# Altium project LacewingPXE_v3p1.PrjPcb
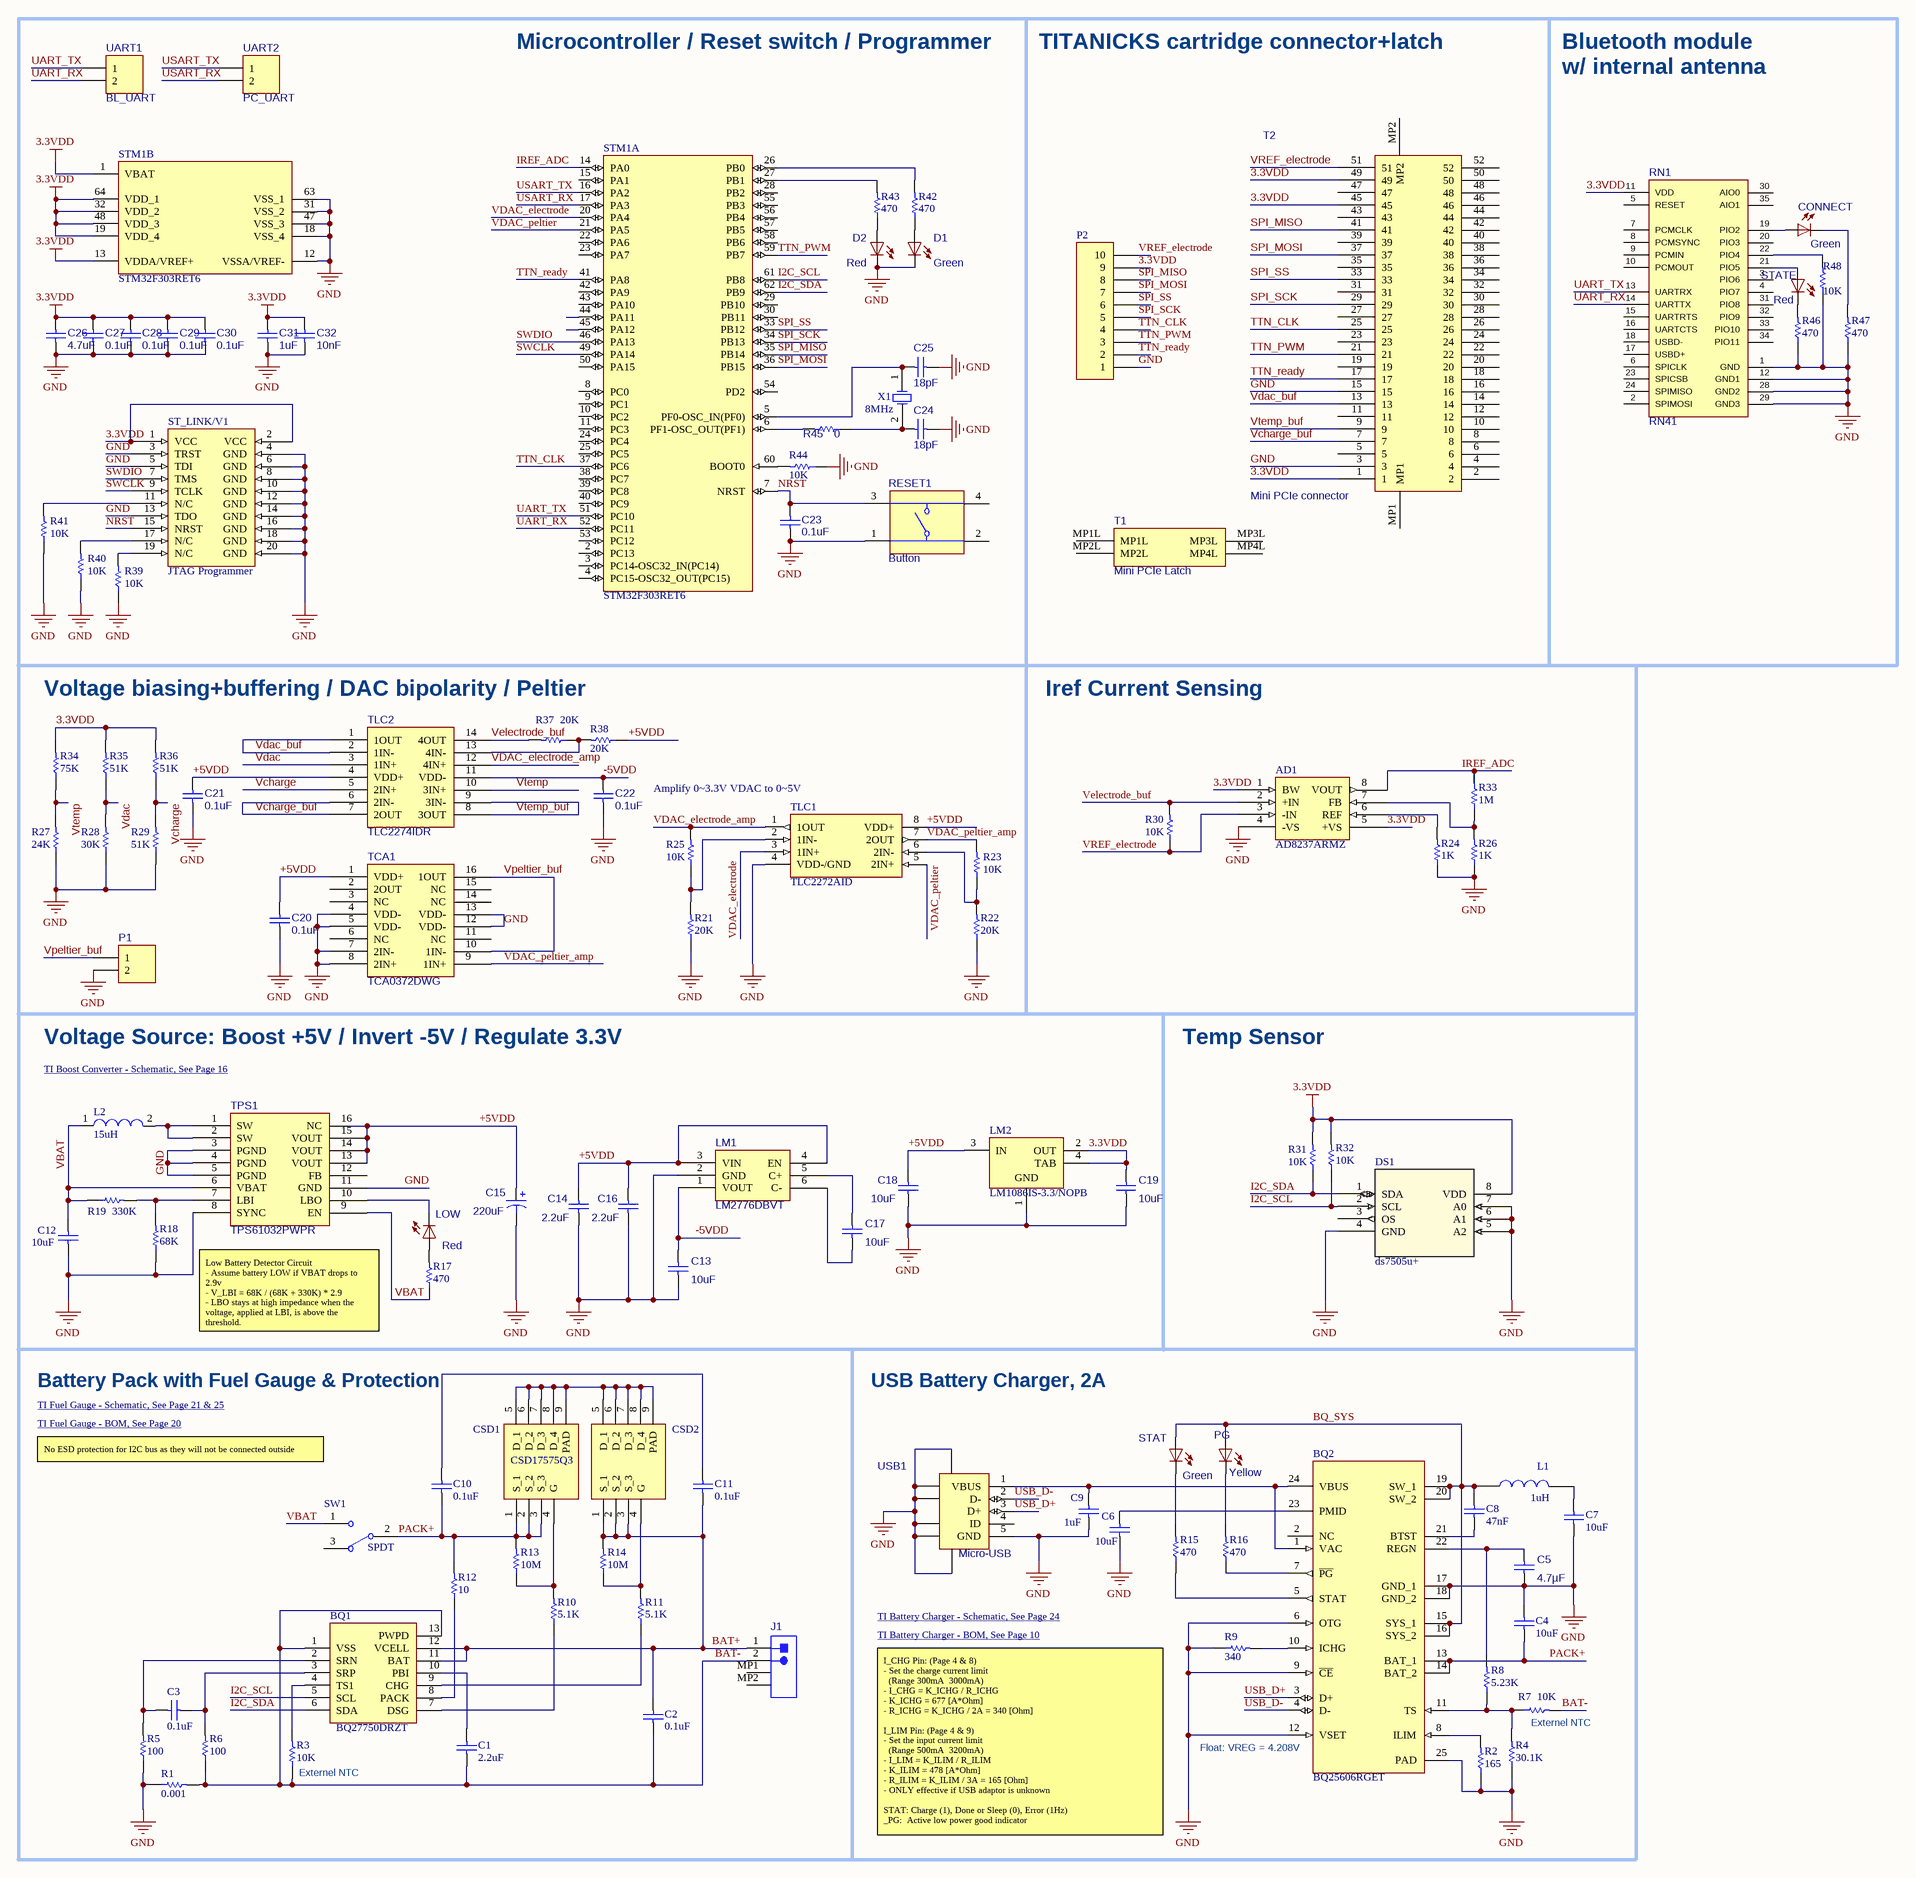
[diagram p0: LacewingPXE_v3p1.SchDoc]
1 sheet, 114 parts. Net scope: global (net labels, ports and power ports of the same name join across sheets).
Board file: LacewingPXE_v3p1.PcbDoc

## Sheet LacewingPXE_v3p1.SchDoc
size A2

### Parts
AD1  AD8237ARMZ  [ADI-RM-8_N]
BQ1  BQ27750DRZT  [BQ27510DRZTG3]
BQ2  BQ25606RGET  [QFN50P400X400X100-25N]
C1  2.2uF  [CAPC1005X55X25NL05T10]
C2  0.1uF  [CAPC1005X56X25LL10T15]
C3  0.1uF  [CAPC1005X56X25LL10T15]
C4  10uF  [CAPC2013X140X50ML20T25]
C5  4.7µF  [CAPC0603(1608)100_N]
C6  10uF  [CAPC2013X95X45NL10T25]
C7  10uF  [CAPC2013X140X50ML20T25]
C8  47nF  [CAPC1005X55X25NL05T10]
C9  1uF  [CAPC2013X95X45NL10T25]
C10  0.1uF  [CAPC1005X56X25LL10T15]
C11  0.1uF  [CAPC1005X56X25LL10T15]
C12  10uF  [CAPC2013X140X50NL20T25]
C13  10uF  [CAPC0805(2012)75_N]
C14  2.2uF  [CAPC0805(2012)75_N]
C15  220uF  [AVX-CAPC7343_V]
C16  2.2uF  [CAPC0805(2012)75_N]
C17  10uF  [CAPC0805(2012)75_N]
C18  10uF  [CAPC0805(2012)75_N]
C19  10uF  [CAPC0805(2012)75_N]
C20  0.1uF  [CAPC0603(1608)100_N]
C21  0.1uF  [CAPC0603(1608)100_N]
C22  0.1uF  [CAPC0603(1608)100_N]
C23  0.1uF  [CAPC0603(1608)100_N]
C24  18pF  [CAPC0603(1608)100_N]
C25  18pF  [CAPC0603(1608)100_N]
C26  4.7uF  [CAPC0603(1608)100_N]
C27  0.1uF  [CAPC0603(1608)100_N]
C28  0.1uF  [CAPC0603(1608)100_N]
C29  0.1uF  [CAPC0603(1608)100_N]
C30  0.1uF  [CAPC0603(1608)100_N]
C31  1uF  [CAPC0603(1608)100_N]
C32  10nF  [CAPC0603(1608)100_N]
CONNECT  Green  [LED-0603]
CSD1  CSD17575Q3  [CSD16327]
CSD2  CSD17575Q3  [CSD16327]  (value not drawn)
D1  Green  [LED-0603]
D2  Red  [LED-0603]
DS1  ds7505u+  [21-0036K]
J1  (no value)  [JST- S2B-PH-SM4-TB(LF)(SN)-2_V]
L1  1uH  [INDC2520X120N]
L2  15uH  [WE-PD 1050]
LM1  LM2776DBVT  [TI-DBV6_M]
LM2  LM1086IS-3.3/NOPB  [KTT0003B_N]
LOW  Red  [LED-0603]
P1  (no value)  [HDR1X2]
P2  (no value)  [HDR1X10]
PG  Yellow  [LED-0603]
R1  0.001  [RESC3216X89X104LL25T25]
R2  165  [RESC1005X40X25NL05T05]
R3  10K  [RESC1005X40X25LL05T05]
R4  30.1K  [RESC1005X40X25LL05T05]
R5  100  [RESC1005X40X25NL05T05]
R6  100  [RESC1005X40X25NL05T05]
R7  10K  [RESC1005X40X25LL05T05]
R8  5.23K  [RESC1005X40X25LL05T05]
R9  340  [RESC1005X40X25LL05T05]
R10  5.1K  [RESC0402(1005)_N]
R11  5.1K  [RESC0402(1005)_N]
R12  10  [RESC1005X40X25NL05T05]
R13  10M  [RESC1005X40X25LL05T05]
R14  10M  [RESC1005X40X25LL05T05]
R15  470  [RESC1005X40X25LL05T05]
R16  470  [RESC1005X40X25LL05T05]
R17  470  [RESC1005X40X25LL05T05]
R18  68K  [RESC1005X40X25ML05T05]
R19  330K  [RESC1005X40X25NL05T05]
R21  20K  [RESC1005X40X25NL05T05]
R22  20K  [RESC1005X40X25NL05T05]
R23  10K  [RESC1005X40X25NL05T05]
R24  1K  [RESC1005X40X25NL05T05]
R25  10K  [RESC1005X40X25NL05T05]
R26  1K  [RESC1005X40X25NL05T05]
R27  24K  [RESC1005X40X25ML05T05]
R28  30K  [RESC1005X40X25LL05T05]
R29  51K  [RESC1005X40X25ML05T05]
R30  10K  [RESC1005X40X25NL05T05]
R31  10K  [RESC1005X40X25NL05T05]
R32  10K  [RESC1005X40X25NL05T05]
R33  1M  [RESC1005X40X25NL05T05]
R34  75K  [RESC1005X40X25LL05T05]
R35  51K  [RESC1005X40X25ML05T05]
R36  51K  [RESC1005X40X25ML05T05]
R37  20K  [RESC1005X40X25NL05T05]
R38  20K  [RESC1005X40X25NL05T05]
R39  10K  [RESC1005X40X25NL05T05]
R40  10K  [RESC1005X40X25NL05T05]
R41  10K  [RESC1005X40X25NL05T05]
R42  470  [RESC1005X40X25LL05T05]
R43  470  [RESC1005X40X25LL05T05]
R44  10K  [RESC1005X40X25NL05T05]
R45  0  [RESC0603(1608)_N]
R46  470  [RESC1005X40X25LL05T05]
R47  470  [RESC1005X40X25LL05T05]
R48  10K  [RESC1005X40X25NL05T05]
RESET1  Button  [OMRON-B3F-1000-4_V]
RN1  RN41  [RN41]
ST_LINK/V1  JTAG Programmer  [JTAG2]
STAT  Green  [LED-0603]
STATE  Red  [LED-0603]
STM1  STM32F303RET6  [STM-LQFP64_V]  (parts A,B of 2)
SW1  SPDT  [1000-SERIES(SPDT)]
T1  Mini PCIe Latch  [Molex Latch-48099]
T2  Mini PCIe connector  [Molex Conn-67910]
TCA1  TCA0372DWG  [ONSC-SOIC-16-751G-03_V]
TLC1  TLC2272AID  [SOIC127P600X175-8N]
TLC2  TLC2274IDR  [TI-D14_M]
TPS1  TPS61032PWPR  [PW0016A_M]
UART1  BL_UART  [HDR1X2]
UART2  PC_UART  [HDR1X2]
USB1  Micro-USB  [HIRO-ZX62R-B-5P_V]
X1  8MHz  [QCL]

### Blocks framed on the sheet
Microcontroller / Reset switch / Programmer: C23-C32 D1 D2 R39-R45 RESET1 ST_LINK/V1 STM1 UART1 UART2 X1
TITANICKS cartridge connector+latch: P2 T1 T2
Voltage biasing+buffering / DAC bipolarity / Peltier: C20-C22 P1 R21-R23 R25 R27-R29 R34-R38 TCA1 TLC1 TLC2
Iref Current Sensing: AD1 R24 R26 R30 R33
Voltage Source: Boost +5V / Invert -5V / Regulate 3.3V: C12-C19 L2 LM1 LM2 LOW R17-R19 TPS1
Temp Sensor: DS1 R31 R32
Battery Pack with Fuel Gauge & Protection: BQ1 C1-C3 C10 C11 CSD1 CSD2 J1 R1 R3 R5 R6 R10-R14 SW1
USB Battery Charger, 2A: BQ2 C4-C9 L1 PG R2 R4 R7-R9 R15 R16 STAT USB1

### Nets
3.3VDD: AD1.1(BW) AD1.5(+VS) C19.1 C26.1 C27.1 C28.1 C29.1 C30.1 C31.1 C32.1 DS1.8(VDD) LM2.2(OUT) LM2.4(TAB) P2.9 R31.2 R32.2 R34.2 R35.2 R36.2 RN1.11(VDD) ST_LINK/V1.1(VCC) ST_LINK/V1.2(VCC) STM1.1(VBAT) STM1.13(VDDA/VREF+) STM1.19(VDD_4) STM1.32(VDD_2) STM1.48(VDD_3) STM1.64(VDD_1) T2.1 T2.45 T2.49
GND: AD1.4(-VS) BQ2.6(OTG) BQ2.9(~{CE}) BQ2.12(VSET) BQ2.17(GND_1) BQ2.18(GND_2) BQ2.25(PAD) C4.2 C5.1 C6.1 C7.1 C9.1 C12.1 C13.2 C14.1 C15.2 C16.1 C18.2 C19.2 C20.2 C21.2 C22.2 C23.2 C24.2 C25.2 C26.2 C27.2 C28.2 C29.2 C30.2 C31.2 C32.2 D1.C D2.C DS1.4(GND) DS1.5(A2) DS1.6(A1) DS1.7(A0) LM1.2(GND) LM2.1(GND) P1.2 P2.1 R1.1 R2.1 R4.1 R5.1 R9.1 R18.1 R21.1 R22.1 R24.1 R26.1 R27.1 R28.1 R29.1 R39.1 R40.1 R41.1 R44.1 R46.1 R47.1 R48.1 RESET1.1 RN1.1(GND) RN1.12(GND1) RN1.28(GND2) RN1.29(GND3) ST_LINK/V1.3(TRST) ST_LINK/V1.4(GND) ST_LINK/V1.5(TDI) ST_LINK/V1.6(GND) ST_LINK/V1.8(GND) ST_LINK/V1.10(GND) ST_LINK/V1.12(GND) ST_LINK/V1.13(TDO) ST_LINK/V1.14(GND) ST_LINK/V1.16(GND) ST_LINK/V1.18(GND) ST_LINK/V1.20(GND) STM1.12(VSSA/VREF-) STM1.18(VSS_4) STM1.31(VSS_2) STM1.47(VSS_3) STM1.63(VSS_1) T2.3 T2.15 TCA1.4(VDD-) TCA1.5(VDD-) TCA1.7(2IN-) TCA1.8(2IN+) TCA1.12(VDD-) TCA1.13(VDD-) TLC1.4(VDD-/GND) TPS1.3(PGND) TPS1.4(PGND) TPS1.5(PGND) TPS1.8(SYNC) TPS1.11(GND) USB1.5(GND) USB1.6(SHLD) USB1.7(SHLD) USB1.8(SHLD) USB1.9(SHLD) USB1.10(SHLD) USB1.11(SHLD)
+5VDD: C14.2 C15.1 C16.2 C18.1 C20.1 C21.1 LM1.3(VIN) LM1.4(EN) LM2.3(IN) R38.1 TCA1.1(VDD+) TLC1.8(VDD+) TLC2.4(VDD+) TPS1.13(VOUT) TPS1.14(VOUT) TPS1.15(VOUT) TPS1.16(NC)
-5VDD: C13.1 C22.1 LM1.1(VOUT) TLC2.11(VDD-)
BAT+: BQ1.11(BAT) BQ1.12(VCELL) C2.2 C11.1 CSD2.1(S_1) CSD2.2(S_2) CSD2.3(S_3) J1.1 R14.2
BAT-: BQ1.1(VSS) BQ1.13(PWPD) C1.1 C2.1 J1.2 R1.2 R3.1 R6.1 R7.2
BQ_SYS: BQ2.15(SYS_1) BQ2.16(SYS_2) BQ2.19(SW_1) BQ2.20(SW_2) C8.2 L1.1 PG.A STAT.A
I2C_SCL: BQ1.5(SCL) DS1.2(SCL) R32.1 STM1.61(PB8)
I2C_SDA: BQ1.6(SDA) DS1.1(SDA) R31.1 STM1.62(PB9)
IREF_ADC: AD1.8(VOUT) R33.2 STM1.14(PA0)
NRST: C23.1 RESET1.3 ST_LINK/V1.15(NRST) STM1.7(NRST)
PACK+: BQ2.13(BAT_1) BQ2.14(BAT_2) C4.1 C10.1 CSD1.1(S_1) CSD1.2(S_2) CSD1.3(S_3) R12.2 R13.2 SW1.2
SPI_MISO: P2.8 STM1.35(PB14) T2.41
SPI_MOSI: P2.7 STM1.36(PB15) T2.37
SPI_SCK: P2.5 STM1.34(PB13) T2.29
SPI_SS: P2.6 STM1.33(PB12) T2.33
SWCLK: ST_LINK/V1.9(TCLK) STM1.49(PA14)
SWDIO: ST_LINK/V1.7(TMS) STM1.46(PA13)
TTN_CLK: P2.4 STM1.37(PC6) T2.25
TTN_PWM: P2.3 STM1.59(PB7) T2.21
TTN_ready: P2.2 STM1.41(PA8) T2.17
UART_RX: RN1.14(UARTTX) STM1.52(PC11) UART1.2
UART_TX: RN1.13(UARTRX) STM1.51(PC10) UART1.1
USART_RX: STM1.17(PA3) UART2.2
USART_TX: STM1.16(PA2) UART2.1
USB_D+: BQ2.3(D+) USB1.3(D+)
USB_D-: BQ2.4(D-) USB1.2(D-)
VBAT: C12.2 L2.1 R17.1 R19.1 SW1.1 TPS1.6(VBAT) TPS1.9(EN)
Vcharge: R29.2 R36.1 TLC2.5(2IN+)
Vcharge_buf: T2.7 TLC2.6(2IN-) TLC2.7(2OUT)
Vdac: R28.2 R35.1 TLC2.3(1IN+)
Vdac_buf: T2.13 TLC2.1(1OUT) TLC2.2(1IN-)
VDAC_electrode: STM1.20(PA4) TLC1.3(1IN+)
VDAC_electrode_amp: R25.2 TLC1.1(1OUT) TLC2.12(4IN+)
VDAC_peltier: STM1.21(PA5) TLC1.5(2IN+)
VDAC_peltier_amp: R23.2 TCA1.9(1IN+) TLC1.7(2OUT)
Velectrode_buf: AD1.2(+IN) R30.2 R37.2 TLC2.14(4OUT)
Vpeltier_buf: P1.1 TCA1.10(1IN-) TCA1.16(1OUT)
VREF_electrode: AD1.3(-IN) P2.10 R30.1 T2.51
Vtemp: R27.2 R34.1 TLC2.10(3IN+)
Vtemp_buf: T2.9 TLC2.8(3OUT) TLC2.9(3IN-)
NetAD1_6: AD1.6(REF) R24.2
NetAD1_7: AD1.7(FB) R26.2 R33.1
NetBQ1_2: BQ1.2(SRN) C3.1 R5.2
NetBQ1_3: BQ1.3(SRP) C3.2 R6.2
NetBQ1_4: BQ1.4(TS1) R3.2
NetBQ1_7: BQ1.7(DSG) R10.1
NetBQ1_8: BQ1.8(PACK) R12.1
NetBQ1_9: BQ1.9(CHG) R11.1
NetBQ1_10: BQ1.10(PBI) C1.2
NetBQ2_1: BQ2.1(VAC) BQ2.24(VBUS) C9.2 USB1.1(VBUS)
NetBQ2_5: BQ2.5(STAT) R15.1
NetBQ2_7: BQ2.7(~{PG}) R16.1
NetBQ2_8: BQ2.8(ILIM) R2.2
NetBQ2_10: BQ2.10(ICHG) R9.2
NetBQ2_11: BQ2.11(TS) R4.2 R7.1 R8.1
NetBQ2_21: BQ2.21(BTST) C8.1
NetBQ2_22: BQ2.22(REGN) C5.2 R8.2
NetBQ2_23: BQ2.23(PMID) C6.2
NetC7_2: C7.2 L1.2
NetC10_2: C10.2 C11.2
NetC17_1: C17.1 LM1.5(C+)
NetC17_2: C17.2 LM1.6(C-)
NetC24_1: C24.1 R45.1 X1.2(OSC2)
NetC25_1: C25.1 STM1.5(PF0-OSC_IN(PF0)) X1.1(OSC1)
NetCONNECT_A: CONNECT.A RN1.19(PIO2)
NetCONNECT_C: CONNECT.C R47.2
NetCSD1_4: CSD1.4(G) R10.2 R13.1
NetCSD1_5: CSD1.5(D_1) CSD1.6(D_2) CSD1.7(D_3) CSD1.8(D_4) CSD1.9(PAD) CSD2.5(D_1) CSD2.6(D_2) CSD2.7(D_3) CSD2.8(D_4) CSD2.9(PAD)
NetCSD2_4: CSD2.4(G) R11.2 R14.1
NetD1_A: D1.A R42.1
NetD2_A: D2.A R43.1
NetL2_2: L2.2 TPS1.1(SW) TPS1.2(SW)
NetLOW_A: LOW.A R17.2
NetLOW_C: LOW.C TPS1.10(LBO)
NetPG_C: PG.C R16.2
NetR15_2: R15.2 STAT.C
NetR18_2: R18.2 R19.2 TPS1.7(LBI)
NetR21_2: R21.2 R25.1 TLC1.2(1IN-)
NetR22_2: R22.2 R23.1 TLC1.6(2IN-)
NetR37_1: R37.1 R38.2 TLC2.13(4IN-)
NetR39_2: R39.2 ST_LINK/V1.19(N/C)
NetR40_2: R40.2 ST_LINK/V1.17(N/C)
NetR41_2: R41.2 ST_LINK/V1.11(N/C)
NetR42_2: R42.2 STM1.26(PB0)
NetR43_2: R43.2 STM1.27(PB1)
NetR44_2: R44.2 STM1.60(BOOT0)
NetR45_2: R45.2 STM1.6(PF1-OSC_OUT(PF1))
NetR46_2: R46.2 STATE.C
NetR48_2: R48.2 RN1.22(PIO4)
NetRN1_21: RN1.21(PIO5) STATE.A

Not connected (* = marked no-connect by the designer): BQ2 2(NC); DS1 3(OS); J1 MP1 MP2; RESET1 2 4; RN1 2(SPIMOSI) 3(PIO6) 4(PIO7) 5(RESET) 6(SPICLK) 7(PCMCLK) 8(PCMSYNC) 9(PCMIN) 10(PCMOUT) 15(UARTRTS) 16(UARTCTS) 17(USBD+) 18(USBD-) 20(PIO3) 23(SPICSB) 24(SPIMISO) 30(AIO0) 31(PIO8) 32(PIO9) 33(PIO10) 34(PIO11) 35(AIO1); STM1 2(PC13) 3(PC14-OSC32_IN(PC14)) 4(PC15-OSC32_OUT(PC15)) 8(PC0) 9(PC1) 10(PC2) 11(PC3) 15(PA1) 22(PA6) 23(PA7) 24(PC4) 25(PC5) 28(PB2) 29(PB10) 30(PB11) 38(PC7) 39(PC8) 40(PC9) 42(PA9) 43(PA10) 44(PA11) 45(PA12) 50(PA15) 53(PC12) 54(PD2) 55(PB3) 56(PB4) 57(PB5) 58(PB6); SW1 3; T1 MP1L MP2L MP3L MP4L; T2 2 4 5 6 8 10 11 12 14 16 18 19 20 22 23 24 26 27 28 30 31 32 34 35 36 38 39 40 42 43 44 46 47 48 50 52 MP1 MP2; TCA1 2(2OUT) 3(NC) 6(NC) 11(NC) 14(NC) 15(NC); TPS1 12(FB); USB1 4(ID)

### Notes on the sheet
- Bluetooth module
- w/ internal antenna
- Amplify 0~3.3V VDAC to 0~5V
- TI Boost Converter - Schematic, See Page 16 <http://www.ti.com/lit/ds/symlink/tps61032.pdf>
- Low Battery Detector Circuit
  - Assume battery LOW if VBAT drops to 2.9v
  - V_LBI = 68K / (68K + 330K) * 2.9
  - LBO stays at high impedance when the voltage, applied at LBI, is above the threshold.
  It is active low when the voltage at LBI goes below 500 mV
- TI Fuel Gauge - Schematic, See Page 21 & 25 <http://www.ti.com/lit/ds/symlink/bq27750.pdf>
- TI Fuel Gauge - BOM, See Page 20 <http://www.ti.com/lit/ug/sluubp4/sluubp4.pdf>
- No ESD protection for I2C bus as they will not be connected outside
- TI Battery Charger - Schematic, See Page 24 <http://www.ti.com/lit/ds/symlink/bq25606.pdf>
- TI Battery Charger - BOM, See Page 10 <http://www.ti.com/lit/ug/sluubl3a/sluubl3a.pdf>
- (near R7) Externel NTC
- (near R3) Externel NTC
- (near BQ2) Float: VREG = 4.208V
- I_CHG Pin: (Page 4 & 8)
  - Set the charge current limit
  (Range 300mA  3000mA)
  - I_CHG = K_ICHG / R_ICHG
  - K_ICHG = 677 [A*Ohm]
  - R_ICHG = K_ICHG / 2A = 340 [Ohm]
  I_LIM Pin: (Page 4 & 9)
  - Set the input current limit
  (Range 500mA  3200mA)
  - I_LIM = K_ILIM / R_ILIM
  - K_ILIM = 478 [A*Ohm]
  - R_ILIM = K_ILIM / 3A = 165 [Ohm]
  - ONLY effective if USB adaptor is unknown
  STAT: Charge (1), Done or Sleep (0), Error (1Hz)
  _PG:  Active low power good indicator

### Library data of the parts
AD1 = AD8237: Instrument Amplifier; Manufacturer: ANALOG DEVICES
BQ1 = BQ27750DRZT: Fuel Gauge and Protection; Manufacturer: TEXAS INSTRUMENTS
BQ2 = BQ25606RGET: Battery Charger; Manufacturer: TEXAS INSTRUMENTS
C1 = CMP-2008-04630-4: CAP 0402; Manufacturer: Murata; Part No: GRM155R60J225KE95D
C2 C3 C10 C11 = CMP-2008-02743-1: CAP 0402; Manufacturer: AVX; Part No: 04026D104KAT2A
C4 C7 = CMP-2007-04702-1: CAP 0805; Manufacturer: AVX; Part No: 0805ZC106KAT2A
C5 = CAP: CAP 0603; Manufacturer: Murata; Part No: GRM188R61C475KAAJD
C6 = CMP-2007-00191-1: CAP 0805; Manufacturer: Murata; Part No: GRM21BC71E106KE11L
C8 = CMP-2008-04630-4: CAP 0402; Manufacturer: Murata; Part No: GRM155R71E473KA88D
C9 = CMP-2007-00191-1: CAP 0805; Manufacturer: Murata; Part No: GRM219R71E105KA88D
C12 = CMP-2007-04643-1: CAP 0805; Manufacturer: AVX; Part No: 08056D106KAT2A
C13 C17-C19 = CMP-1036-00002-1: CAP 0805; Manufacturer: Wurth Electronics; Part No: 885012107010
C14 C16 = CMP-1036-00002-1: CAP 0805; Manufacturer: Multicomp; Part No: MC0805B225K250CT
C15 = CMP-0279-00002-1: CAP 2917; Manufacturer: AVX; Part No: TAJD227K010RNJ
C20-C23 C27-C30 = CMP-1035-00032-1: CAP 0603; Manufacturer: Multicomp; Part No: MC0603B104K500CT
C24 C25 = CMP-1035-00032-1: CAP 0603; Manufacturer: KEMET; Part No: C0603C180K5RACTU
C26 = CMP-1035-00032-1: CAP 0603; Manufacturer: AVX; Part No: 06036D475KAT2A
C31 = CMP-1035-00032-1: CAP 0603; Manufacturer: AVX; Part No: 06033D105KAT2A
C32 = CMP-1035-00032-1: CAP 0603; Manufacturer: KEMET; Part No: C0603C103K5RAC7081
CONNECT D1 = LED0603: LED SMD 0603; Manufacturer: KingBright; Part No: KPT-1608SGC
CSD1 CSD2 = CSD17575Q3: MOSFET; Manufacturer: Texas Instruments; Part No: CSD17575Q3T
D2 LOW STATE = LED0603: LED SMD 0603; Manufacturer: KingBright; Part No: KPT-1608SECK-J3
DS1 = ds7505u+: Digital Thermometer; Manufacturer: Maxim
J1 = CN-1P-2M-R2: Battery Connector; Manufacturer: JST; Part No: S2B-PH-SM4-TB(LF)(SN)
L1 = DFE252012F-1R0M=P2: Inductor; Manufacturer: Murata
L2 = CMP-1396-00032-1: Power Inductor; Manufacturer: Wurth Elektronik; Part No: 7447714150
LM1 = LM2776: Voltage Inverter -5V; Manufacturer: Texas Instruments
LM2 = CMP-0062-00552-5: 1.5A 3.3V LDO; Manufacturer: Texas Instruments
P1 UART1 UART2 = Header 2: Header, 2-Pin
P2 = Header 10: Header, 10-Pin
PG = LED0603: LED SMD 0603; Manufacturer: Kingbright; Part No: KPT-1608SYCK-J3
R1 = CMP-1666-00018-2: RES 1206; Manufacturer: Vishay; Part No: WSLP12061L000FEA
R2 = CMP-2002-08233-1: RES 0402; Manufacturer: Vishay Dale; Part No: CRCW0402165RFKED
R3 R7 = CMP-2002-01179-1: Thermistor RES 0402; Manufacturer: Panasonic; Part No: ERTJ0EG103FA
R4 = CMP-2002-08506-3: RES 0402; Manufacturer: Vishay; Part No: CRCW040230K1FKED
R5 R6 = CMP-2002-08127-1: RES 0402; Manufacturer: Vishay; Part No: CRCW0402100RFKED
R8 = CMP-2002-00118-3: RES 0402; Manufacturer: Vishay; Part No: CRCW04025K23FKED
R9 = CMP-2002-00876-1: RES 0402; Manufacturer: Panasonic; Part No: ERJ2RKF3400X
R10 R11 = CMP-1011-00590-1: RES 0402; Manufacturer: Vishay; Part No: CRCW04025K10FKED
R12 = CMP-2002-08143-1: RES 0402; Manufacturer: Vishay Dale; Part No: CRCW040210R0FKED
R13 R14 = CMP-2002-08141-1: RES 0402; Manufacturer: Vishay; Part No: CRCW040210M0FKED
R15-R17 R42 R43 R46 R47 = CMP-2002-00022-1: RES 0402; Manufacturer: Vishay; Part No: CRCW0402470RFKED
R18 = CMP-2002-00170-1: RES 0402; Manufacturer: Vishay; Part No: CRCW040268K0FKED
R19 = CMP-2002-08521-1: RES 0402; Manufacturer: Vishay; Part No: CRCW0402330KFKED
R21 R22 R37 R38 = CMP-2002-08356-1: RES 0402; Manufacturer: Vishay; Part No: CRCW040220K0FKED
R23 R25 R30-R32 R39-R41 R44 R48 = CMP-2002-08135-1: RES 0402; Manufacturer: Vishay; Part No: CRCW040210K0FKED
R24 R26 = CMP-2002-08276-1: RES 0402; Manufacturer: Vishay; Part No: CRCW04021K00FKED
R27 = CMP-2002-08403-1: RES 0402; Manufacturer: Vishay Dale; Part No: CRCW040224K0FKED
R28 = CMP-2002-08504-1: RES 0402; Manufacturer: Vishay Dale; Part No: CRCW040230K0FKED
R29 R35 R36 = CMP-2002-00078-1: RES 0402; Manufacturer: Vishay Dale; Part No: CRCW040251K0FKED
R33 = CMP-2002-08314-1: RES 0402; Manufacturer: Vishay; Part No: CRCW04021M00FKED
R34 = CMP-2002-00208-1: RES 0402; Manufacturer: Vishay Dale; Part No: CRCW040275K0FKED
R45 = CMP-1012-00514-1: RES 0603; Manufacturer: Multicomp; Part No: MC0603SAF0000T5E
RESET1 = SW-SPST-4_A: Manufacturer: OMRON; Part No: B3F-1022
RN1 = BLUETOOTH-RN41: RN41 Bluetooth Module; Part No: RN41-I/RM
ST_LINK/V1 = JTAG: Manufacturer: AMPHENOL; Part No: T821120A1S100CEU
STAT = LED0603: LED SMD 0603; Manufacturer: Kingbright; Part No: KPT-1608SGC
STM1 = STM32F303RBT6_1: ARM Cortex-M4 32-bit MCU; Manufacturer: STMICROELECTRONICS
SW1 = 1101M1S3ZQE2: Manufacturer: C & K COMPONENTS
T1 = Mini PCIe Latch: Manufacturer: MOLEX; Part No: 48099-5701
T2 = Mini PCIe connector: Manufacturer: MOLEX; Part No: 67910-5700
TCA1 = TCA0372: Dual High-Power OPAMP; Manufacturer: ON SEMICONDUCTOR
TLC1 = TLC2272AID: Dual OPAMP; Manufacturer: TEXAS INSTRUMENTS
TLC2 = TLC2274: Quad OPAMP; Manufacturer: TEXAS INSTRUMENTS
TPS1 = TPS61032: Voltage Boost +5V; Manufacturer: TEXAS INSTRUMENTS
USB1 = CMP-0031-00001-1: ZX62R-B-5P; Manufacturer: Hirose; Part No: ZX62R-B-5P(30)
X1 = XTAL: Crystal Oscillator; Manufacturer: QANTEK TECHNOLOGY CORPORATION; Part No: QCL8.00000F18B23B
